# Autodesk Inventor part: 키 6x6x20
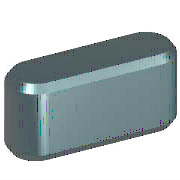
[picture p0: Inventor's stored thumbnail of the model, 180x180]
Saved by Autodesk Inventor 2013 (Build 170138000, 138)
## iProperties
Created: 2012-02
Part Number: 키 6x6x20
Material: 강철, 연강
Document SubType Name: Modeling
Standard: JIS B 1301
Designer: mdu-01
Standards Organization: JIS
Language: ko-KR
Size Designation: 6x6x20
Categories: <MemberInstance><Categories><Category DisplayName="샤프트 부품" InternalName="7f7aeb1f-a693-4053-b835-cee3144e0d98" Mnemonic="SHFT"><Category DisplayName="키" Interna
Density: 1 g/cm^3
IsCustomPart: 1
Author: mdu-01
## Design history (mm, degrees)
workplane "Work Plane1"
workplane "Work Plane2"
sketch "스케치1"
  geometry: L1 (3, 3)-(17, 3); L2 (17, -3)-(3, -3); L3 (0, 9.4)-(0, -7.4) reference; L4 (-5, 0)-(30, 0) reference; L5 (20, 0)-(20, 7); A1 r 3 centre (3, 0) between (3, 3) and (3, -3); A2 r 3 centre (17, 0) between (17, -3) and (17, 3)
  constraints: 6 end point, 5 point on circle, 4 tangent, 3 point on line, 2 centre point, 1 horizontal, 1 parallel, 1 perpendicular
  dimensions: "d0" = 3 radius of A1 (= 0.5 x PB); "d13" = 3 radius of A2 (= 0.5 x PB); "d14" = 20 distance between parallel lines of L5 L3 (= NLG)
extrude "본체1" new body sketch "스케치1" taper "d3" = 0 deg; stored distance "d4" = 10
workplane "Work Plane3"
body "Solid1"
chamfer "모따기1" distance "d8" = 0.4 (= PHH); stored, may be unused: second distance "d9" = 0.4 (= PHH), angle "d15" = 45 deg
other parameters: "d1" = -3.5 (= -PNT), "d2" = 2.5 (= PH - PNT), "NLG" = 20 [user parameter; used in 3 equation terms], "PB" = 6 [user parameter; used in 2 equation terms], "PNT" = 3.5 [user parameter; used in 2 equation terms], "PH" = 6 [user parameter; used in 1 equation term], "PHH" = 0.4 [user parameter; used in 2 equation terms], "d10" = 0, "d16" = 0, "d17" = 0, "d18" = 0, "WDMIN" = 17 [user parameter], "WDMAX" = 22 [user parameter], "RR" = 0.16 [user parameter], "PUEB" = 2.8 [user parameter]
